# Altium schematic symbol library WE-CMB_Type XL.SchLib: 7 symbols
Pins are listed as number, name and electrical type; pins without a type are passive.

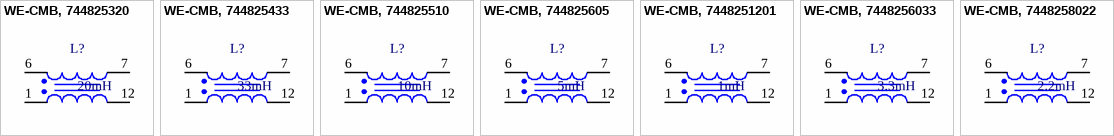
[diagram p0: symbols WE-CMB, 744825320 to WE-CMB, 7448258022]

## WE-CMB, 744825320
designator L?, comment 20mH
WE-CMB Common Mode Power Line Choke, Type XL, 20mH; PartNumber: 744825320
footprint WE-CMB_Type XL
pins: 1, 6, 7, 12

## WE-CMB, 744825433
designator L?, comment 33mH
WE-CMB Common Mode Power Line Choke, Type XL, 33mH; PartNumber: 744825433
footprint WE-CMB_Type XL
pins: 1, 6, 7, 12

## WE-CMB, 744825510
designator L?, comment 10mH
WE-CMB Common Mode Power Line Choke, Type XL, 10mH; PartNumber: 744825510
footprint WE-CMB_Type XL
pins: 1, 6, 7, 12

## WE-CMB, 744825605
designator L?, comment 5mH
WE-CMB Common Mode Power Line Choke, Type XL, 5mH; PartNumber: 744825605
footprint WE-CMB_Type XL
pins: 1, 6, 7, 12

## WE-CMB, 7448251201
designator L?, comment 1mH
WE-CMB Common Mode Power Line Choke, Type XL, 1mH; PartNumber: 7448251201
footprint WE-CMB_Type XL_7448251201
pins: 1, 6, 7, 12

## WE-CMB, 7448256033
designator L?, comment 3.3mH
WE-CMB Common Mode Power Line Choke, Type XL, 3.3mH; PartNumber: 7448256033
footprint WE-CMB_Type XL
pins: 1, 6, 7, 12

## WE-CMB, 7448258022
designator L?, comment 2.2mH
WE-CMB Common Mode Power Line Choke, Type XL, 2.2mH; PartNumber: 7448258022
footprint WE-CMB_Type XL
pins: 1, 6, 7, 12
